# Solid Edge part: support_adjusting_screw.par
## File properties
Title: Solid Edge 20
Author: vicky raina
Template: Normal.par
Last saved by: Robert a Rhodes jr
Revision: 6
Application: Solid Edge
Material: aluminum
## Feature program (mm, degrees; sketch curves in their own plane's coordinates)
sketch for "unnamed Protrusion 1" plane through (0, 0, 0) normal (0, -1, 0) x-axis (1, 0, 0)
  circle centre (0, 0) radius 38.1
extrude "unnamed Protrusion 1" add finite 584.2 along +normal
sketch for "unnamed Cutout 1" plane through (0, -521.208, 0) normal (0, -1, 0) x-axis (1, 0, 0)
extrude "unnamed Cutout 1" cut finite 76.2 along +normal
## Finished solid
Body 1: solid body, 5 faces, 4 edges, 0 vertices.
  Faces by surface: plane 3, cylinder 2
  Edges by curve: circle 4
Bounding box of the edges (mm): 76.200 x 584.200 x 76.200, from (-38.1, -584.2, -38.1) to (38.1, 0, 38.1).
Cylindrical faces by radius (mm): R25.4 x1, R38.1 x1
Planar faces by outward normal: +y 1, -y 2
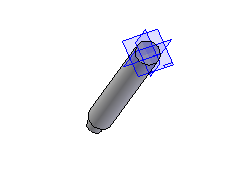
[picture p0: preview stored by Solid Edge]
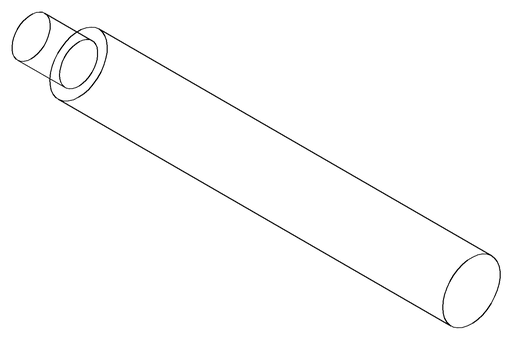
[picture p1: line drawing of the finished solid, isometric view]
